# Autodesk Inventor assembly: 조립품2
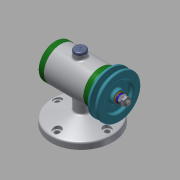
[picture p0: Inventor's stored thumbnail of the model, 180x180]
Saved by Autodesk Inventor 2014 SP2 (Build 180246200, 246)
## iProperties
Created: 2018-12
Part Number: 조립품2
Document SubType Name: Assembly
Designer: 거성
Author: 거성
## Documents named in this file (15)
- C:\Users\거성\Desktop\481208V1017\조립품2.iam
- C:\Users\거성\Desktop\481208V1017\V벨트풀리.ipt
- C:\Users\거성\Desktop\481208V1017\고무캡.ipt
- C:\Users\거성\Desktop\481208V1017\너트 M8.ipt
- 너트 M8.ipt
- C:\Users\거성\Desktop\481208V1017\뒤커버.ipt
- C:\Users\거성\Desktop\481208V1017\베어링 15 x 32 x 9.ipt
- C:\Users\거성\Desktop\481208V1017\본체.ipt
- C:\Users\거성\Desktop\481208V1017\볼트 M4 x 12.ipt
- C:\Users\거성\Desktop\481208V1017\스프링와셔 8.ipt
- C:\Users\거성\Desktop\481208V1017\앞커버.ipt
- C:\Users\거성\Desktop\481208V1017\오일 실 15 25 7.ipt
- C:\Users\거성\Desktop\481208V1017\와셔 8x17.ipt
- C:\Users\거성\Desktop\481208V1017\축.ipt
- C:\Users\거성\Desktop\481208V1017\키 3 x 3 x 12.ipt
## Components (2 placed, 2 different names)
1. V벨트풀리:1
2. 고무캡:1
